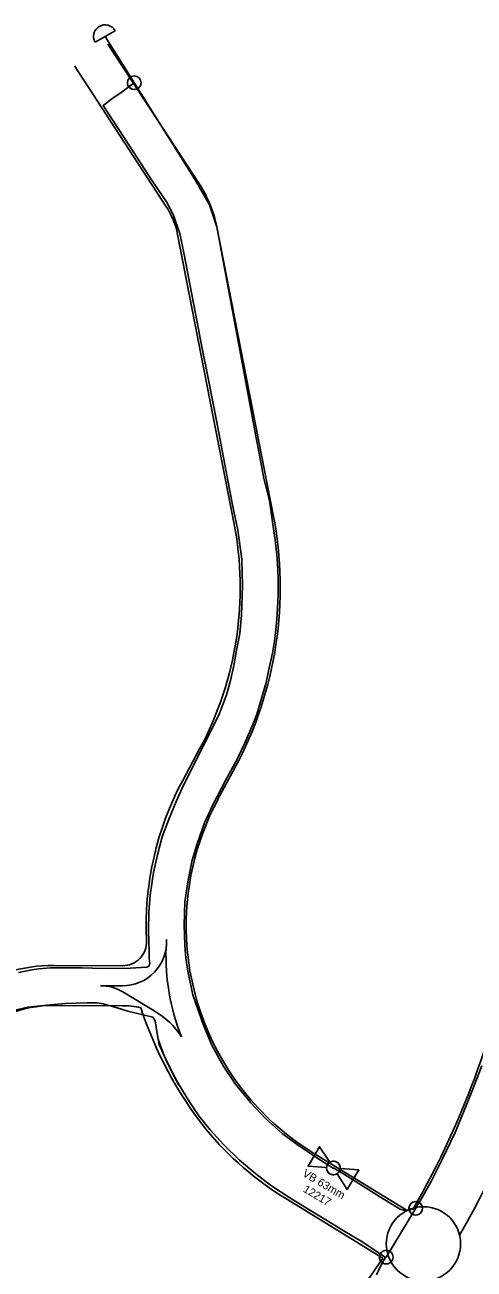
# Model space of a CAD drawing. Extents: x 325709 to 364434, y 7573432 to 7597073.
# Drawn here: x 329372.4 to 329540.8, y 7586994.5 to 7587461 of the extents above; entities that cross this region are included whole.
import ezdxf

# ---------------------------------------------------------------- set-up
doc = ezdxf.new("R2010")
doc.units = 0
for name, color, linetype in [('LOGRADOURO', 7, 'Continuous'), ('SIMBOLO', 7, 'Continuous'), ('TUBO_PEAD_GN_63', 7, 'Continuous'), ('VALVULA_PEAD_63', 7, 'Continuous'), ('VES - BLOQUEIIO', 7, 'Continuous')]:
    doc.layers.add(name, color=color, linetype=linetype)

# ---------------------------------------------------------------- blocks, each defined once
blk = doc.blocks.new('VALVULA_PEAD_DN_63')
at = {"layer": 'VALVULA_PEAD_63'}
for points in [[(-1.14, 0.57), (-4.25, 2.13), (-4.25, -2.13), (-1.14, -0.57)], [(-1.14, -0.57), (-4.25, -2.13), (-4.25, 2.13), (-1.14, 0.57)], [(1.14, -0.57), (4.25, -2.13), (4.25, 2.13), (1.14, 0.57)], [(1.14, -0.57), (4.25, -2.13), (4.25, 2.13), (1.14, 0.57)]]:
    blk.add_lwpolyline(points, dxfattribs=at)
blk.add_circle((0, 0), 1.28, dxfattribs=at)
for start, end in [(90, 270), (153.4349, 206.5651), (270, 90), (0, 26.5651), (333.4349, 0)]:
    blk.add_arc((0, 0), 1.28, start, end, dxfattribs=at)
blk = doc.blocks.new('INTERLIGACAO')
at = {"layer": 'SIMBOLO'}
blk.add_circle((0, 0), 1.28, dxfattribs=at)
for start, end in [(0, 180), (180, 0)]:
    blk.add_arc((0, 0), 1.28, start, end, dxfattribs=at)

msp = doc.modelspace()

# ---------------------------------------------------------------- linework, layer by layer
at = {"layer": 'LOGRADOURO'}
for p, q in [((329403.52, 7587453.78), (329437.84, 7587401.25)), ((329390.96, 7587445.58), (329425.28, 7587393.04)), ((329429.61, 7587382.4), (329450.74, 7587274.43)), ((329444.33, 7587385.28), (329465.46, 7587277.31)), ((329437.9, 7587189.54), (329431.57, 7587177.76)), ((329451.11, 7587182.43), (329444.78, 7587170.66)), ((329383.37, 7587108.37), (329408.95, 7587108.24)), ((329400.7, 7587100.78), (329408.91, 7587100.74)), ((329420.88, 7587091.34), (329409.13, 7587098.41)), ((329383.29, 7587093.37), (329408.87, 7587093.24)), ((329515.7, 7587016.53), (329480.63, 7587038)), ((329506.55, 7586998.68), (329470.19, 7587020.94))]:
    msp.add_line(p, q, dxfattribs=at)
msp.add_circle((329521.78, 7587004.01), 13.92, dxfattribs=at)
msp.add_circle((329521.78, 7587004.01), 13.92, dxfattribs=at)
for centre, radius, start, end in [((329400.17, 7587376.63), 45, 11.0764, 33.1566), ((329400.17, 7587376.63), 30, 11.0764, 33.1566), ((329325.62, 7587249.94), 127.5, 331.7236, 11.0764), ((329325.62, 7587249.94), 142.5, 331.7236, 11.0764), ((329532.85, 7587123.28), 115, 151.7236, 182.7955), ((329532.85, 7587123.28), 100, 151.7236, 182.7955), ((329231.68, 7587181.39), 330.06, 330.2156, 350.1811), ((329231.67, 7587181.4), 350.07, 330.1585, 350.1814), ((329409, 7587117.24), 16.5, 269.7086, 2.7955), ((329409, 7587117.24), 9, 269.7086, 2.7955), ((329532.85, 7587123.28), 100, 182.7955, 219.5499), ((329509.8, 7587112.28), 84.52, 178.2353, 201.3151), ((329383.06, 7587048.37), 60, 89.7086, 123.4809), ((329400.62, 7587084.28), 16.5, 58.9447, 89.7086), ((329383.06, 7587048.37), 45, 89.7086, 134.7685), ((329410.08, 7587071.77), 21.5, 74.4195, 93.2092), ((329555.19, 7587137.87), 146.54, 198.0437, 218.3861), ((329406.96, 7587066.64), 28.35, 31.7521, 60.5925), ((329532.85, 7587123.28), 100, 219.5499, 238.5222), ((329532.85, 7587123.28), 120, 219.5499, 238.5222), ((329231.68, 7587181.4), 330.06, 281.0807, 326.3865)]:
    msp.add_arc(centre, radius, start, end, dxfattribs=at)
at = {"layer": 'TUBO_PEAD_GN_63'}
for p, q in [((329398.69, 7587454.45), (329406.22, 7587458.79)), ((329507.83, 7586999.03), (329518.87, 7587017.31)), ((329507.83, 7586999.03), (329518.87, 7587017.31))]:
    msp.add_line(p, q, dxfattribs=at)
for points in [[(329459.11, 7587306.2), (329444.33, 7587385.28), (329441.54, 7587393.51), (329436.26, 7587402.91), (329402.46, 7587456.62)], [(329453.02, 7587232.84), (329453.63, 7587239.62), (329454, 7587250.62), (329453.69, 7587260.72), (329452.19, 7587271.53), (329450.27, 7587281.07), (329448.65, 7587289.57), (329444.23, 7587312.6), (329441.19, 7587327.85), (329438.61, 7587340.84), (329436.94, 7587349.58), (329434.96, 7587359.88), (329432.09, 7587374.91), (329430.45, 7587382.8), (329427.96, 7587389.88), (329425.52, 7587394.59), (329420.14, 7587402.53), (329411.64, 7587415.64), (329401.79, 7587430.75), (329402.61, 7587431.43), (329404.93, 7587433.23), (329408.44, 7587435.65), (329413.37, 7587439.29)], [(329453.02, 7587232.84), (329453.63, 7587239.62), (329454, 7587250.62), (329453.69, 7587260.72), (329452.19, 7587271.53), (329450.27, 7587281.07), (329448.65, 7587289.57), (329444.23, 7587312.6), (329441.19, 7587327.85), (329438.61, 7587340.84), (329436.94, 7587349.58), (329434.96, 7587359.88), (329432.09, 7587374.91), (329430.45, 7587382.8), (329427.96, 7587389.88), (329425.52, 7587394.59), (329420.14, 7587402.53), (329411.64, 7587415.64), (329401.79, 7587430.75), (329402.61, 7587431.43), (329404.93, 7587433.23), (329408.44, 7587435.65), (329412.43, 7587438.6)], [(329452.19, 7587186.16), (329454.75, 7587191.43), (329456.19, 7587194.92), (329457.56, 7587198.07), (329459.29, 7587202.56), (329460.96, 7587208.02), (329462.85, 7587214.5), (329463.88, 7587219.29), (329465.2, 7587225.46), (329465.96, 7587229.92), (329466.42, 7587234.12), (329466.77, 7587238.24), (329467.13, 7587242.4), (329467.29, 7587247.41), (329467.39, 7587252.32), (329467.22, 7587257.23), (329466.83, 7587262.35), (329466.19, 7587267.97), (329465.29, 7587273.81), (329464.05, 7587282.61), (329462.01, 7587290.89), (329460.15, 7587300.37), (329459.11, 7587306.2)], [(329452.19, 7587186.16), (329454.75, 7587191.43), (329456.19, 7587194.92), (329457.56, 7587198.07), (329459.29, 7587202.56), (329460.96, 7587208.02), (329462.85, 7587214.5), (329463.88, 7587219.29), (329465.2, 7587225.46), (329465.96, 7587229.92), (329466.42, 7587234.12), (329466.77, 7587238.24), (329467.13, 7587242.4), (329467.29, 7587247.41), (329467.39, 7587252.32), (329467.22, 7587257.23), (329466.83, 7587262.35), (329466.19, 7587267.97), (329465.29, 7587273.81), (329464.05, 7587282.61), (329462.01, 7587290.89), (329460.15, 7587300.37), (329459.11, 7587306.2)], [(329453.02, 7587232.84), (329451.62, 7587225.92), (329450.82, 7587221.25), (329449.49, 7587215.19), (329447.94, 7587209.87), (329445.3, 7587202.79), (329442.14, 7587196.2), (329439.26, 7587190.51), (329435.35, 7587182.89), (329431.32, 7587174.81), (329429.12, 7587169.77), (329426.21, 7587162.84), (329423.86, 7587156.63), (329422.05, 7587149.82), (329420.62, 7587143.27), (329419.37, 7587134.65), (329418.91, 7587128.34), (329418.74, 7587121.3), (329418.95, 7587113.55), (329418.98, 7587110.96), (329419.27, 7587109.21), (329419, 7587108.19), (329418.14, 7587107.68), (329412.02, 7587107.35), (329401.8, 7587107.26)], [(329453.02, 7587232.84), (329451.62, 7587225.92), (329450.82, 7587221.25), (329449.49, 7587215.19), (329447.94, 7587209.87), (329445.3, 7587202.79), (329442.14, 7587196.2), (329439.26, 7587190.51), (329435.35, 7587182.89), (329431.32, 7587174.81), (329429.12, 7587169.77), (329426.21, 7587162.84), (329423.86, 7587156.63), (329422.05, 7587149.82), (329420.62, 7587143.27), (329419.37, 7587134.65), (329418.91, 7587128.34), (329418.74, 7587121.3), (329418.95, 7587113.55), (329418.98, 7587110.96), (329419.27, 7587109.21), (329419, 7587108.19), (329418.14, 7587107.68), (329412.02, 7587107.35), (329401.8, 7587107.26)], [(329543.61, 7587070.67), (329539.9, 7587061.08), (329537.1, 7587053.95), (329533.67, 7587045.76), (329528.78, 7587035.57), (329524.66, 7587027.37), (329520.59, 7587020.07), (329518.63, 7587017.18), (329517.18, 7587016.85), (329514.68, 7587016.55), (329513.02, 7587017), (329506.64, 7587020.86), (329492.25, 7587030), (329488.23, 7587032.37), (329487.96, 7587032.38), (329482.19, 7587035.98), (329474.48, 7587041.23), (329468.87, 7587045.4), (329462.41, 7587051.15), (329457.12, 7587056.85), (329451.39, 7587063.9), (329447.02, 7587070.37), (329442.62, 7587078.22), (329439.37, 7587085.92), (329435.35, 7587097.32), (329433.49, 7587106.17), (329432.71, 7587111.07), (329432.32, 7587116.01), (329432.13, 7587123.47), (329432.41, 7587132.21), (329433.45, 7587139.65), (329435.15, 7587147.87), (329436.96, 7587153.99), (329439.74, 7587161.82), (329442.86, 7587168.63), (329447.75, 7587177.95), (329450.45, 7587182.9), (329452.19, 7587186.16)], [(329401.8, 7587107.26), (329393.71, 7587107.51), (329390.12, 7587107.48), (329386.48, 7587107.51), (329382.05, 7587107.44), (329377.61, 7587107.07), (329374.96, 7587106.68), (329370.06, 7587105.77)], [(329401.8, 7587107.26), (329393.71, 7587107.51), (329390.12, 7587107.48), (329386.48, 7587107.51), (329382.05, 7587107.44), (329377.61, 7587107.07), (329374.96, 7587106.68), (329370.06, 7587105.77)], [(329387.54, 7587094.05), (329380.64, 7587093.46), (329373.52, 7587092.67), (329368.1, 7587091.42), (329363.15, 7587089.55), (329357.65, 7587086.36), (329356.92, 7587085.8)], [(329387.54, 7587094.05), (329380.64, 7587093.46), (329373.52, 7587092.67), (329368.1, 7587091.42), (329363.15, 7587089.55), (329357.65, 7587086.36), (329356.92, 7587085.8)], [(329387.54, 7587094.05), (329395.72, 7587094.32), (329399.47, 7587094.31), (329401.77, 7587093.93), (329406.94, 7587092.48), (329411.01, 7587091.27), (329420.36, 7587089.03), (329421.21, 7587087.65), (329422.05, 7587082.09), (329422.7, 7587078.76), (329425.69, 7587072), (329428.23, 7587066.95), (329430.14, 7587063.43)], [(329387.54, 7587094.05), (329395.72, 7587094.32), (329399.47, 7587094.31), (329401.77, 7587093.93), (329406.94, 7587092.48), (329411.01, 7587091.27), (329420.36, 7587089.03), (329421.21, 7587087.65), (329422.05, 7587082.09), (329422.7, 7587078.76), (329425.69, 7587072), (329428.23, 7587066.95), (329430.14, 7587063.43)], [(329499.07, 7587004.64), (329491.72, 7587009), (329485.16, 7587013), (329478.85, 7587016.89), (329471.74, 7587021.29), (329464.5, 7587025.95), (329458.94, 7587030.25), (329452.83, 7587035.4), (329446.81, 7587041.18), (329441.8, 7587046.72), (329437.64, 7587051.98), (329433.56, 7587058), (329430.03, 7587064.03), (329428.67, 7587066.26), (329424.61, 7587074.45), (329422.3, 7587080.73)], [(329499.07, 7587004.64), (329491.72, 7587009), (329485.16, 7587013), (329478.85, 7587016.89), (329471.74, 7587021.29), (329464.5, 7587025.95), (329458.94, 7587030.25), (329452.83, 7587035.4), (329446.81, 7587041.18), (329441.8, 7587046.72), (329437.64, 7587051.98), (329433.56, 7587058), (329430.03, 7587064.03), (329428.67, 7587066.26), (329424.61, 7587074.45), (329422.3, 7587080.73)], [(329499.07, 7587004.64), (329507.56, 7586998.85), (329505.97, 7586996.11), (329504.23, 7586992.4)], [(329499.07, 7587004.64), (329507.56, 7586998.85), (329505.97, 7586996.11), (329504.23, 7586992.4)]]:
    msp.add_lwpolyline(points, dxfattribs=at)
msp.add_arc((329402.46, 7587456.62), 4.35, 29.9675, 209.9675, dxfattribs=at)

# ---------------------------------------------------------------- block references
at = {"layer": 'SIMBOLO', "xscale": 1.9999999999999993, "yscale": 1.9999999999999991, "rotation": 0.14972222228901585}
for p in [(329413.37, 7587439.29), (329518.87, 7587017.31), (329507.83, 7586999.03)]:
    msp.add_blockref('INTERLIGACAO', p, dxfattribs=at)
at = {"layer": 'VES - BLOQUEIIO', "xscale": 1.9999999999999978, "yscale": 1.9999999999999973, "rotation": -30.58094237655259}
msp.add_blockref('VALVULA_PEAD_DN_63', (329488.03, 7587032.42), dxfattribs=at)

# ---------------------------------------------------------------- texts
for s, p in [('VB 63mm', (329476.17, 7587029.57)), ('12217', (329476.42, 7587023.7))]:
    msp.add_text(s, height=3, rotation=329.4191).set_placement(p)

doc.saveas('drawing.dxf')
